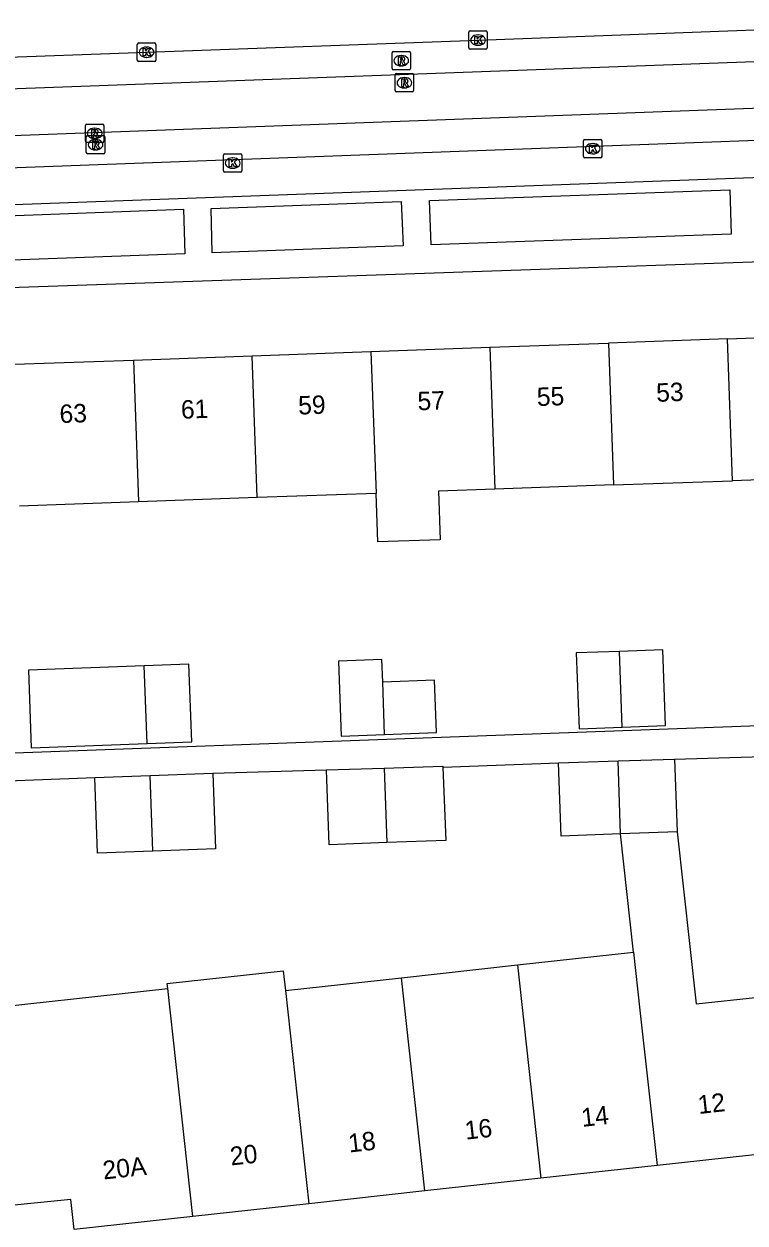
# Model space of a CAD drawing. Extents: x 160557 to 161245, y 385330 to 386505.
# Drawn here: x 160755.5 to 160794.6, y 386089.9 to 386154.9 of the extents above; entities that cross this region are included whole.
import ezdxf

# ---------------------------------------------------------------- set-up
doc = ezdxf.new("R2010")
doc.units = 0
for name, color, linetype in [('IMGEO_Kolk', 7, 'Continuous'), ('IMGEO_Pand', 7, 'Continuous'), ('IMGEO_Pand_nummerreeks', 7, 'Continuous'), ('IMGEO_Rijbaan_lokaal_gesloten', 7, 'Continuous'), ('IMGEO_Rijbaan_lokaal_open', 7, 'Continuous'), ('IMGEO_Rioolput', 7, 'Continuous'), ('IMGEO_Voetpad_open', 7, 'Continuous')]:
    doc.layers.add(name, color=color, linetype=linetype)

msp = doc.modelspace()

# ---------------------------------------------------------------- linework, layer by layer
at = {"layer": 'IMGEO_Kolk'}
for p, q in [((160779.589, 386153.629), (160779.589, 386154.481)), ((160779.664, 386154.555), (160780.516, 386154.555)), ((160780.077, 386154.335), (160780.102, 386154.335)), ((160780.59, 386154.481), (160780.59, 386153.629)), ((160761.599, 386152.972), (160761.599, 386153.824)), ((160761.674, 386153.898), (160762.526, 386153.898)), ((160762.087, 386153.678), (160762.112, 386153.678)), ((160762.6, 386153.824), (160762.6, 386152.972)), ((160780.516, 386153.555), (160779.664, 386153.555)), ((160780.1, 386153.775), (160780.075, 386153.775)), ((160762.526, 386152.898), (160761.674, 386152.898)), ((160762.11, 386153.118), (160762.085, 386153.118)), ((160785.811, 386147.737), (160785.811, 386148.589)), ((160785.886, 386148.663), (160786.738, 386148.663)), ((160786.299, 386148.443), (160786.324, 386148.443)), ((160786.812, 386148.589), (160786.812, 386147.737)), ((160766.271, 386146.958), (160766.271, 386147.81)), ((160766.346, 386147.884), (160767.198, 386147.884)), ((160766.759, 386147.664), (160766.784, 386147.664)), ((160767.272, 386147.81), (160767.272, 386146.958)), ((160786.738, 386147.663), (160785.886, 386147.663)), ((160786.322, 386147.883), (160786.297, 386147.883)), ((160766.782, 386147.104), (160766.757, 386147.104)), ((160767.198, 386146.884), (160766.346, 386146.884))]:
    msp.add_line(p, q, dxfattribs=at)
for points in [[(160779.589, 386153.629), (160779.589, 386154.481)], [(160779.664, 386154.555), (160780.516, 386154.555)], [(160779.91, 386154.255), (160780.033, 386154.255), (160780.033, 386154.104), (160780.163, 386154.255), (160780.327, 386154.255), (160780.181, 386154.104), (160780.334, 386153.855), (160780.182, 386153.855), (160780.097, 386154.019), (160780.033, 386153.952), (160780.033, 386153.855), (160779.91, 386153.855), (160779.91, 386154.255)], [(160780.59, 386154.481), (160780.59, 386153.629)], [(160761.599, 386152.972), (160761.599, 386153.824)], [(160761.674, 386153.898), (160762.526, 386153.898)], [(160761.92, 386153.598), (160762.043, 386153.598), (160762.043, 386153.447), (160762.173, 386153.598), (160762.337, 386153.598), (160762.191, 386153.447), (160762.344, 386153.198), (160762.192, 386153.198), (160762.107, 386153.362), (160762.043, 386153.295), (160762.043, 386153.198), (160761.92, 386153.198), (160761.92, 386153.598)], [(160762.6, 386153.824), (160762.6, 386152.972)], [(160780.516, 386153.555), (160779.664, 386153.555)], [(160762.526, 386152.898), (160761.674, 386152.898)], [(160785.811, 386147.737), (160785.811, 386148.589)], [(160785.886, 386148.663), (160786.738, 386148.663)], [(160786.132, 386148.363), (160786.255, 386148.363), (160786.255, 386148.212), (160786.385, 386148.363), (160786.549, 386148.363), (160786.403, 386148.212), (160786.556, 386147.963), (160786.404, 386147.963), (160786.319, 386148.127), (160786.255, 386148.06), (160786.255, 386147.963), (160786.132, 386147.963), (160786.132, 386148.363)], [(160786.812, 386148.589), (160786.812, 386147.737)], [(160766.271, 386146.958), (160766.271, 386147.81)], [(160766.346, 386147.884), (160767.198, 386147.884)], [(160767.272, 386147.81), (160767.272, 386146.958)], [(160786.738, 386147.663), (160785.886, 386147.663)], [(160766.592, 386147.584), (160766.715, 386147.584), (160766.715, 386147.433), (160766.845, 386147.584), (160767.009, 386147.584), (160766.863, 386147.433), (160767.016, 386147.184), (160766.864, 386147.184), (160766.779, 386147.348), (160766.715, 386147.281), (160766.715, 386147.184), (160766.592, 386147.184), (160766.592, 386147.584)], [(160767.198, 386146.884), (160766.346, 386146.884)]]:
    msp.add_lwpolyline(points, dxfattribs=at)
for centre, start, end in [((160779.666, 386154.479), 91.55205, 178.44795), ((160779.666, 386154.479), 91.55205, 178.44795), ((160780.514, 386154.479), 1.55205, 88.44795), ((160780.514, 386154.479), 1.55205, 88.44795), ((160761.676, 386153.822), 91.55205, 178.44795), ((160761.676, 386153.822), 91.55205, 178.44795), ((160762.524, 386153.822), 1.55205, 88.44795), ((160762.524, 386153.822), 1.55205, 88.44795), ((160779.666, 386153.631), 181.55205, 268.44795), ((160779.666, 386153.631), 181.55205, 268.44795), ((160780.514, 386153.631), 271.55205, 358.44795), ((160780.514, 386153.631), 271.55205, 358.44795), ((160761.676, 386152.974), 181.55205, 268.44795), ((160761.676, 386152.974), 181.55205, 268.44795), ((160762.524, 386152.974), 271.55205, 358.44795), ((160762.524, 386152.974), 271.55205, 358.44795), ((160785.888, 386148.587), 91.55205, 178.44795), ((160785.888, 386148.587), 91.55205, 178.44795), ((160786.736, 386148.587), 1.55205, 88.44795), ((160786.736, 386148.587), 1.55205, 88.44795), ((160766.348, 386147.808), 91.55205, 178.44795), ((160766.348, 386147.808), 91.55205, 178.44795), ((160767.196, 386147.808), 1.55205, 88.44795), ((160767.196, 386147.808), 1.55205, 88.44795), ((160785.888, 386147.739), 181.55205, 268.44795), ((160785.888, 386147.739), 181.55205, 268.44795), ((160786.736, 386147.739), 271.55205, 358.44795), ((160786.736, 386147.739), 271.55205, 358.44795), ((160766.348, 386146.96), 181.55205, 268.44795), ((160766.348, 386146.96), 181.55205, 268.44795), ((160767.196, 386146.96), 271.55205, 358.44795), ((160767.196, 386146.96), 271.55205, 358.44795)]:
    msp.add_arc(centre, 0.0765, start, end, dxfattribs=at)
for centre, major_axis, ratio, start_param, end_param in [((160780.076, 386154.055), (-0.387, 0.002), 0.722429, 4.712389, 7.853982), ((160780.101, 386154.055), (-0.39, 0.002), 0.717154, 1.570796, 4.712389), ((160762.086, 386153.398), (-0.387, 0.002), 0.722429, 4.712389, 7.853982), ((160762.111, 386153.398), (-0.39, 0.002), 0.717154, 1.570796, 4.712389), ((160786.298, 386148.163), (-0.387, 0.002), 0.722429, 4.712389, 7.853982), ((160786.323, 386148.163), (-0.39, 0.002), 0.717154, 1.570796, 4.712389), ((160766.758, 386147.384), (-0.387, 0.002), 0.722429, 4.712389, 7.853982), ((160766.783, 386147.384), (-0.39, 0.002), 0.717154, 1.570796, 4.712389)]:
    msp.add_ellipse(centre, major_axis=major_axis, ratio=ratio, start_param=start_param, end_param=end_param, dxfattribs=at)
at = {"layer": 'IMGEO_Pand'}
for points in [[(160793.614, 386137.848), (160787.168, 386137.618)], [(160793.614, 386137.848), (160800.06, 386138.078)], [(160793.889, 386130.152), (160793.614, 386137.848)], [(160774.276, 386137.158), (160780.722, 386137.388)], [(160780.722, 386137.388), (160787.168, 386137.618)], [(160780.722, 386137.388), (160780.997, 386129.693)], [(160787.168, 386137.618), (160787.443, 386129.923)], [(160754.939, 386136.469), (160761.385, 386136.699)], [(160761.385, 386136.699), (160767.831, 386136.929)], [(160761.385, 386136.699), (160761.66, 386129.004)], [(160767.831, 386136.929), (160774.276, 386137.158)], [(160768.106, 386129.233), (160767.831, 386136.929)], [(160774.276, 386137.158), (160774.551, 386129.463)], [(160787.443, 386129.923), (160793.889, 386130.152)], [(160800.335, 386130.382), (160793.889, 386130.152)], [(160774.551, 386129.463), (160768.106, 386129.233)], [(160780.997, 386129.693), (160777.939, 386129.584), (160778.033, 386126.952), (160774.645, 386126.831), (160774.551, 386129.463)], [(160787.443, 386129.923), (160780.997, 386129.693)], [(160761.66, 386129.004), (160755.214, 386128.774)], [(160768.106, 386129.233), (160761.66, 386129.004)], [(160787.913, 386116.781), (160790.263, 386116.867), (160790.111, 386120.977), (160787.766, 386120.891)], [(160774.917, 386119.222), (160774.873, 386120.446), (160772.518, 386120.359), (160772.669, 386116.296), (160775.018, 386116.382)], [(160787.766, 386120.891), (160785.413, 386120.805), (160785.565, 386116.695), (160787.913, 386116.781)], [(160787.913, 386116.781), (160787.766, 386120.891)], [(160761.977, 386120.109), (160755.687, 386119.879), (160755.842, 386115.651), (160762.128, 386115.886)], [(160762.128, 386115.886), (160764.56, 386115.977), (160764.404, 386120.197), (160761.977, 386120.109)], [(160762.128, 386115.886), (160761.977, 386120.109)], [(160775.018, 386116.382), (160777.837, 386116.485), (160777.731, 386119.327), (160774.917, 386119.222)], [(160775.018, 386116.382), (160774.917, 386119.222)], [(160771.86, 386114.47), (160774.989, 386114.564)], [(160775.129, 386110.518), (160772.011, 386110.401), (160771.86, 386114.47)], [(160774.989, 386114.564), (160778.181, 386114.66), (160778.183, 386114.618)], [(160774.989, 386114.564), (160775.129, 386110.518)], [(160778.183, 386114.618), (160778.33, 386110.638), (160775.129, 386110.518)], [(160784.453, 386114.85), (160787.683, 386114.947)], [(160787.82, 386110.992), (160784.6, 386110.872), (160784.453, 386114.85)], [(160787.683, 386114.947), (160790.751, 386115.04)], [(160787.82, 386110.992), (160787.683, 386114.947)], [(160790.751, 386115.04), (160790.897, 386111.107)], [(160759.295, 386114.058), (160762.293, 386114.164)], [(160762.436, 386110.05), (160759.441, 386109.944), (160759.295, 386114.058)], [(160762.293, 386114.164), (160765.695, 386114.285)], [(160762.436, 386110.05), (160762.293, 386114.164)], [(160765.695, 386114.285), (160765.841, 386110.171), (160762.436, 386110.05)], [(160790.897, 386111.107), (160787.82, 386110.992)], [(160788.524, 386104.573), (160787.82, 386110.992)], [(160790.897, 386111.107), (160791.925, 386101.768), (160795.31, 386102.141), (160795.404, 386101.287), (160795.69, 386098.684), (160796.137, 386094.618), (160796.237, 386093.713), (160789.797, 386093.005)], [(160782.228, 386103.881), (160788.524, 386104.573)], [(160788.524, 386104.573), (160788.869, 386101.432), (160789.797, 386093.005)], [(160763.255, 386102.611), (160763.227, 386102.869), (160769.522, 386103.561), (160769.639, 386102.496)], [(160775.934, 386103.189), (160782.228, 386103.881)], [(160782.228, 386103.881), (160782.574, 386100.74), (160783.502, 386092.312)], [(160769.639, 386102.496), (160775.934, 386103.189)], [(160777.208, 386091.62), (160775.934, 386103.189)], [(160764.618, 386090.235), (160758.18, 386089.527), (160758.001, 386091.154), (160752.756, 386090.626), (160751.677, 386101.337), (160763.255, 386102.611)], [(160764.618, 386090.235), (160763.255, 386102.611)], [(160769.639, 386102.496), (160770.913, 386090.928)], [(160789.797, 386093.005), (160783.502, 386092.312)], [(160783.502, 386092.312), (160777.208, 386091.62)], [(160777.208, 386091.62), (160770.913, 386090.928)], [(160770.913, 386090.928), (160764.618, 386090.235)]]:
    msp.add_lwpolyline(points, dxfattribs=at)
at = {"layer": 'IMGEO_Rijbaan_lokaal_gesloten'}
for points in [[(160725.861, 386152.062), (160744.095, 386152.749), (160762.105, 386153.4), (160780.09, 386154.054), (160796.064, 386154.65), (160826.115, 386155.745), (160832.121, 386155.974), (160833.979, 386156.036)], [(160689.851, 386149.047), (160748.65, 386151.198), (160802.504, 386153.169), (160827.576, 386154.097), (160834.064, 386154.328)], [(160834.176, 386151.782), (160735.181, 386148.132), (160703.104, 386146.996)], [(160806.476, 386149.019), (160734.993, 386146.392)]]:
    msp.add_lwpolyline(points, dxfattribs=at)
at = {"layer": 'IMGEO_Rijbaan_lokaal_open'}
for points in [[(160735.717, 386128.079), (160736.193, 386114.703), (160798.286, 386116.987)], [(160790.751, 386115.04), (160800.984, 386115.348)], [(160765.695, 386114.285), (160771.86, 386114.47)], [(160778.183, 386114.618), (160784.453, 386114.85)], [(160750.284, 386113.703), (160759.295, 386114.058)]]:
    msp.add_lwpolyline(points, dxfattribs=at)
at = {"layer": 'IMGEO_Rioolput'}
for p, q in [((160775.419, 386152.51), (160775.419, 386153.362)), ((160775.494, 386153.436), (160776.346, 386153.436)), ((160775.907, 386153.216), (160775.932, 386153.216)), ((160776.42, 386153.362), (160776.42, 386152.51)), ((160776.346, 386152.436), (160775.494, 386152.436)), ((160775.592, 386151.315), (160775.592, 386152.167)), ((160775.667, 386152.241), (160776.519, 386152.241)), ((160775.93, 386152.656), (160775.905, 386152.656)), ((160776.593, 386152.167), (160776.593, 386151.315)), ((160776.08, 386152.021), (160776.105, 386152.021)), ((160776.519, 386151.241), (160775.667, 386151.241)), ((160776.103, 386151.461), (160776.078, 386151.461)), ((160758.784, 386148.565), (160758.784, 386149.417)), ((160758.859, 386149.491), (160759.711, 386149.491)), ((160759.272, 386149.271), (160759.297, 386149.271)), ((160759.785, 386149.417), (160759.785, 386148.565)), ((160758.833, 386147.953), (160758.833, 386148.805)), ((160759.711, 386148.491), (160758.859, 386148.491)), ((160758.908, 386148.879), (160759.76, 386148.879)), ((160759.295, 386148.711), (160759.27, 386148.711)), ((160759.321, 386148.659), (160759.346, 386148.659)), ((160759.834, 386148.805), (160759.834, 386147.953)), ((160759.76, 386147.879), (160758.908, 386147.879)), ((160759.344, 386148.099), (160759.319, 386148.099))]:
    msp.add_line(p, q, dxfattribs=at)
for points in [[(160775.419, 386152.51), (160775.419, 386153.362)], [(160775.494, 386153.436), (160776.346, 386153.436)], [(160776.008, 386153.134), (160775.756, 386153.136), (160775.756, 386152.736)], [(160775.756, 386152.736), (160775.88, 386152.736), (160775.88, 386152.898), (160775.891, 386152.898)], [(160775.934, 386153.055), (160775.88, 386153.055), (160775.88, 386152.974)], [(160775.88, 386152.974), (160775.932, 386152.974)], [(160775.938, 386152.869), (160776.009, 386152.736), (160776.149, 386152.736), (160776.084, 386152.862)], [(160776.42, 386153.362), (160776.42, 386152.51)], [(160776.346, 386152.436), (160775.494, 386152.436)], [(160775.592, 386151.315), (160775.592, 386152.167)], [(160775.667, 386152.241), (160776.519, 386152.241)], [(160776.593, 386152.167), (160776.593, 386151.315)], [(160776.181, 386151.939), (160775.929, 386151.941), (160775.929, 386151.541)], [(160775.929, 386151.541), (160776.053, 386151.541), (160776.053, 386151.703), (160776.064, 386151.703)], [(160776.107, 386151.86), (160776.053, 386151.86), (160776.053, 386151.779)], [(160776.053, 386151.779), (160776.105, 386151.779)], [(160776.111, 386151.674), (160776.182, 386151.541), (160776.322, 386151.541), (160776.257, 386151.667)], [(160776.519, 386151.241), (160775.667, 386151.241)], [(160758.784, 386148.565), (160758.784, 386149.417)], [(160758.859, 386149.491), (160759.711, 386149.491)], [(160759.373, 386149.189), (160759.121, 386149.191), (160759.121, 386148.791)], [(160759.121, 386148.791), (160759.245, 386148.791), (160759.245, 386148.953), (160759.256, 386148.953)], [(160759.299, 386149.11), (160759.245, 386149.11), (160759.245, 386149.029)], [(160759.245, 386149.029), (160759.297, 386149.029)], [(160759.303, 386148.924), (160759.374, 386148.791), (160759.514, 386148.791), (160759.449, 386148.917)], [(160759.785, 386149.417), (160759.785, 386148.565)], [(160758.833, 386147.953), (160758.833, 386148.805)], [(160759.711, 386148.491), (160758.859, 386148.491)], [(160758.908, 386148.879), (160759.76, 386148.879)], [(160759.422, 386148.577), (160759.17, 386148.579), (160759.17, 386148.179)], [(160759.17, 386148.179), (160759.294, 386148.179), (160759.294, 386148.341), (160759.305, 386148.341)], [(160759.348, 386148.498), (160759.294, 386148.498), (160759.294, 386148.417)], [(160759.294, 386148.417), (160759.346, 386148.417)], [(160759.352, 386148.312), (160759.423, 386148.179), (160759.563, 386148.179), (160759.498, 386148.305)], [(160759.834, 386148.805), (160759.834, 386147.953)], [(160759.76, 386147.879), (160758.908, 386147.879)]]:
    msp.add_lwpolyline(points, dxfattribs=at)
for centre, radius, start, end in [((160775.496, 386153.36), 0.0765, 91.55205, 178.44795), ((160775.496, 386153.36), 0.0765, 91.55205, 178.44795), ((160775.89, 386152.845), 0.0533, 26.02933, 88.69889), ((160775.916, 386153.163), 0.19, 274.7715, 282.96867), ((160775.94, 386152.959), 0.0964, 77.00612, 93.18647), ((160775.954, 386153.016), 0.0378, 276.66336, 79.67722), ((160776.007, 386153.024), 0.109, 350.36119, 89.41601), ((160776.005, 386153.024), 0.112, 277.58423, 350.98172), ((160775.989, 386152.809), 0.108, 29.51342, 73.79051), ((160776.344, 386153.36), 0.0765, 1.55205, 88.44795), ((160776.344, 386153.36), 0.0765, 1.55205, 88.44795), ((160775.496, 386152.512), 0.0765, 181.55205, 268.44795), ((160775.496, 386152.512), 0.0765, 181.55205, 268.44795), ((160775.669, 386152.165), 0.0765, 91.55205, 178.44795), ((160775.669, 386152.165), 0.0765, 91.55205, 178.44795), ((160776.344, 386152.512), 0.0765, 271.55205, 358.44795), ((160776.344, 386152.512), 0.0765, 271.55205, 358.44795), ((160776.517, 386152.165), 0.0765, 1.55205, 88.44795), ((160776.517, 386152.165), 0.0765, 1.55205, 88.44795), ((160776.063, 386151.65), 0.0533, 26.02933, 88.69889), ((160776.089, 386151.968), 0.19, 274.7715, 282.96867), ((160776.113, 386151.764), 0.0964, 77.00612, 93.18647), ((160776.127, 386151.821), 0.0378, 276.66336, 79.67722), ((160776.18, 386151.829), 0.109, 350.36119, 89.41601), ((160776.178, 386151.829), 0.112, 277.58423, 350.98172), ((160776.162, 386151.614), 0.108, 29.51342, 73.79051), ((160775.669, 386151.317), 0.0765, 181.55205, 268.44795), ((160775.669, 386151.317), 0.0765, 181.55205, 268.44795), ((160776.517, 386151.317), 0.0765, 271.55205, 358.44795), ((160776.517, 386151.317), 0.0765, 271.55205, 358.44795), ((160758.861, 386149.415), 0.0765, 91.55205, 178.44795), ((160758.861, 386149.415), 0.0765, 91.55205, 178.44795), ((160759.255, 386148.9), 0.0533, 26.02933, 88.69889), ((160759.281, 386149.218), 0.19, 274.7715, 282.96867), ((160759.305, 386149.014), 0.0964, 77.00612, 93.18647), ((160759.319, 386149.071), 0.0378, 276.66336, 79.67722), ((160759.372, 386149.079), 0.109, 350.36119, 89.41601), ((160759.37, 386149.079), 0.112, 277.58423, 350.98172), ((160759.354, 386148.864), 0.108, 29.51342, 73.79051), ((160759.709, 386149.415), 0.0765, 1.55205, 88.44795), ((160759.709, 386149.415), 0.0765, 1.55205, 88.44795), ((160758.861, 386148.567), 0.0765, 181.55205, 268.44795), ((160758.861, 386148.567), 0.0765, 181.55205, 268.44795), ((160758.91, 386148.803), 0.0765, 91.55205, 178.44795), ((160758.91, 386148.803), 0.0765, 91.55205, 178.44795), ((160759.304, 386148.288), 0.0533, 26.02933, 88.69889), ((160759.33, 386148.606), 0.19, 274.7715, 282.96867), ((160759.354, 386148.402), 0.0964, 77.00612, 93.18647), ((160759.368, 386148.459), 0.0378, 276.66336, 79.67722), ((160759.421, 386148.467), 0.109, 350.36119, 89.41601), ((160759.419, 386148.467), 0.112, 277.58423, 350.98172), ((160759.403, 386148.252), 0.108, 29.51342, 73.79051), ((160759.709, 386148.567), 0.0765, 271.55205, 358.44795), ((160759.709, 386148.567), 0.0765, 271.55205, 358.44795), ((160759.758, 386148.803), 0.0765, 1.55205, 88.44795), ((160759.758, 386148.803), 0.0765, 1.55205, 88.44795), ((160758.91, 386147.955), 0.0765, 181.55205, 268.44795), ((160758.91, 386147.955), 0.0765, 181.55205, 268.44795), ((160759.758, 386147.955), 0.0765, 271.55205, 358.44795), ((160759.758, 386147.955), 0.0765, 271.55205, 358.44795)]:
    msp.add_arc(centre, radius, start, end, dxfattribs=at)
for centre, major_axis, ratio, start_param, end_param in [((160775.906, 386152.936), (-0.387, 0.002), 0.722429, 4.712389, 7.853982), ((160775.931, 386152.936), (-0.39, 0.002), 0.717154, 1.570796, 4.712389), ((160776.079, 386151.741), (-0.387, 0.002), 0.722429, 4.712389, 7.853982), ((160776.104, 386151.741), (-0.39, 0.002), 0.717154, 1.570796, 4.712389), ((160759.271, 386148.991), (-0.387, 0.002), 0.722429, 4.712389, 7.853982), ((160759.296, 386148.991), (-0.39, 0.002), 0.717154, 1.570796, 4.712389), ((160759.32, 386148.379), (-0.387, 0.002), 0.722429, 4.712389, 7.853982), ((160759.345, 386148.379), (-0.39, 0.002), 0.717154, 1.570796, 4.712389)]:
    msp.add_ellipse(centre, major_axis=major_axis, ratio=ratio, start_param=start_param, end_param=end_param, dxfattribs=at)
at = {"layer": 'IMGEO_Voetpad_open'}
for points in [[(160805.905, 386147.009), (160804.896, 386146.94), (160736.079, 386144.436), (160735.35, 386144.409)], [(160777.457, 386145.358), (160793.753, 386145.932), (160793.826, 386143.523), (160777.538, 386142.948), (160777.457, 386145.358)], [(160765.61, 386144.925), (160775.923, 386145.295), (160775.977, 386144.118), (160776.027, 386142.887), (160765.67, 386142.51), (160765.61, 386144.925)], [(160747.766, 386144.265), (160764.098, 386144.882), (160764.177, 386142.466), (160747.847, 386141.862), (160747.766, 386144.265)], [(160735.299, 386139.972), (160806.477, 386142.421), (160809.404, 386142.522)]]:
    msp.add_lwpolyline(points, dxfattribs=at)

# ---------------------------------------------------------------- texts
at = {"layer": 'IMGEO_Pand_nummerreeks'}
for s, rotation, p in [('55', 2.04171, (160783.294, 386134.198)), ('53', 2.03973, (160789.769, 386134.429)), ('59', 2.04171, (160770.345, 386133.736)), ('57', 2.04171, (160776.819, 386133.967)), ('63', 2.04171, (160757.396, 386133.275)), ('61', 2.04171, (160763.983, 386133.51)), ('12', 6.27962, (160792.065, 386095.79)), ('14', 6.27962, (160785.744, 386095.094)), ('16', 6.2769, (160779.42, 386094.399)), ('18', 6.2769, (160773.1, 386093.704)), ('20', 6.2769, (160766.686, 386092.999)), ('20A', 6.2769, (160759.776, 386092.238))]:
    msp.add_text(s, height=1, rotation=rotation, dxfattribs=at).set_placement(p)

doc.saveas('drawing.dxf')
